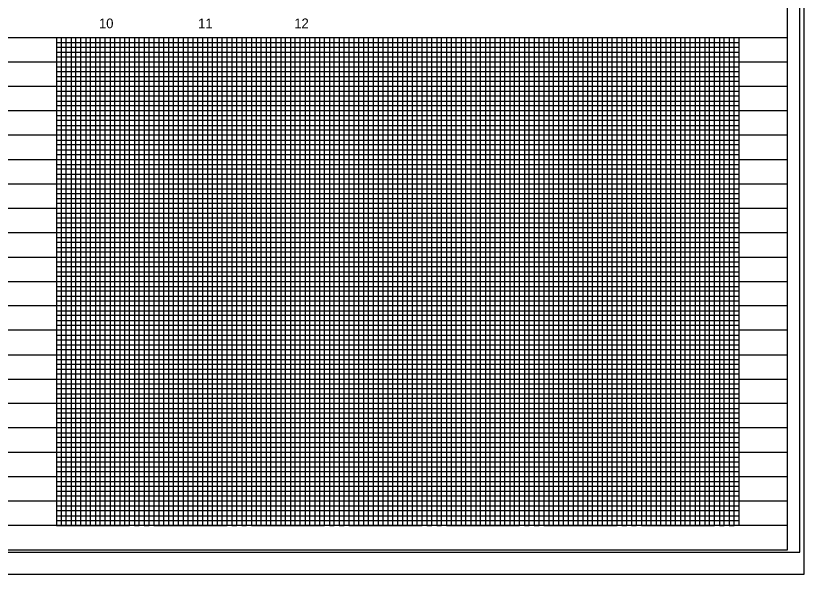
# Model space of a CAD drawing. Extents: x 1019474 to 1021158, y 503201 to 504732.
# Drawn here: x 1020350 to 1021158, y 503201 to 503773 of the extents above; entities that cross this region are included whole.
import ezdxf

# ---------------------------------------------------------------- set-up
doc = ezdxf.new("R2010")
doc.units = 0
for name, color, linetype in [('Exist Vertical Profile Horizontal Axis Label Major', 7, 'Continuous'), ('Sheet Cutting Line CELL', 7, 'Continuous'), ('Sheet Layout Profile Border Port 2', 7, 'Continuous'), ('Sheet Plot Border Inside CELL', 7, 'Continuous'), ('Sheet Plot Border Outside CELL', 7, 'Continuous'), ('Sheet Profile CELL', 7, 'Continuous'), ('Sheet Profile Grid Major CELL', 7, 'Continuous'), ('Sheet Profile Grid Middle CELL', 7, 'Continuous'), ('Sheet Profile Grid Minor CELL', 7, 'Continuous')]:
    doc.layers.add(name, color=color, linetype=linetype)

msp = doc.modelspace()

# ---------------------------------------------------------------- linework, layer by layer
at = {"layer": 'Sheet Cutting Line CELL'}
msp.add_line((1019474.22, 503200.7), (1021158.22, 503200.7), dxfattribs=at)
at = {"layer": 'Sheet Layout Profile Border Port 2'}
msp.add_lwpolyline([(1019691.22, 503750.7), (1021091.22, 503750.7), (1021091.22, 503250.7), (1019691.22, 503250.7)], close=True, dxfattribs=at)
at = {"layer": 'Sheet Plot Border Inside CELL'}
msp.add_lwpolyline([(1019487.22, 503223.15), (1021153.72, 503223.15), (1021153.72, 504278.25), (1019487.22, 504278.25)], close=True, dxfattribs=at)
at = {"layer": 'Sheet Plot Border Outside CELL'}
msp.add_lwpolyline([(1019474.22, 503200.7), (1021158.22, 503200.7), (1021158.22, 504300.7), (1019474.22, 504300.7)], close=True, dxfattribs=at)
at = {"layer": 'Sheet Profile CELL'}
for p, q in [((1019641.22, 503750.7), (1021141.22, 503750.7)), ((1021141.22, 503250.7), (1019641.22, 503250.7)), ((1019641.22, 503225.7), (1021141.22, 503225.7))]:
    msp.add_line(p, q, dxfattribs=at)
msp.add_lwpolyline([(1021141.22, 504275.7), (1019641.22, 504275.7), (1019641.22, 503225.7), (1021141.22, 503225.7)], close=True, dxfattribs=at)
at = {"layer": 'Sheet Profile Grid Major CELL'}
for p, q in [((1020341.22, 503750.7), (1020391.22, 503750.7)), ((1020441.22, 503750.7), (1020491.22, 503750.7)), ((1020541.22, 503750.7), (1020591.22, 503750.7)), ((1020641.22, 503750.7), (1020691.22, 503750.7)), ((1020741.22, 503750.7), (1020791.22, 503750.7)), ((1020841.22, 503750.7), (1020891.22, 503750.7)), ((1020941.22, 503750.7), (1020991.22, 503750.7)), ((1021041.22, 503750.7), (1021091.22, 503750.7)), ((1021041.22, 503250.7), (1021041.22, 503250.7))]:
    msp.add_line(p, q, dxfattribs=at)
for points in [[(1020341.22, 503750.7), (1020391.22, 503750.7), (1020391.22, 503250.7), (1020441.22, 503250.7), (1020441.22, 503750.7), (1020491.22, 503750.7), (1020491.22, 503250.7), (1020541.22, 503250.7), (1020541.22, 503750.7), (1020591.22, 503750.7), (1020591.22, 503250.7), (1020641.22, 503250.7), (1020641.22, 503750.7), (1020691.22, 503750.7), (1020691.22, 503250.7), (1020741.22, 503250.7), (1020741.22, 503750.7), (1020791.22, 503750.7), (1020791.22, 503250.7), (1020841.22, 503250.7), (1020841.22, 503750.7), (1020891.22, 503750.7), (1020891.22, 503250.7), (1020941.22, 503250.7), (1020941.22, 503750.7), (1020991.22, 503750.7), (1020991.22, 503250.7), (1021041.22, 503250.7), (1021041.22, 503250.7), (1021041.22, 503750.7), (1021091.22, 503750.7), (1021091.22, 503250.7)], [(1021141.22, 503700.7), (1019641.22, 503700.7)], [(1021141.22, 503650.7), (1019641.22, 503650.7), (1019641.22, 503600.7), (1021141.22, 503600.7)], [(1021141.22, 503550.7), (1019641.22, 503550.7), (1019641.22, 503500.7), (1021141.22, 503500.7)], [(1021141.22, 503450.7), (1019641.22, 503450.7), (1019641.22, 503400.7), (1021141.22, 503400.7)], [(1021141.22, 503350.7), (1019641.22, 503350.7), (1019641.22, 503350.7), (1019641.22, 503300.7), (1021141.22, 503300.7)], [(1021141.22, 503250.7), (1019641.22, 503250.7)]]:
    msp.add_lwpolyline(points, dxfattribs=at)
at = {"layer": 'Sheet Profile Grid Middle CELL'}
for points in [[(1020391.22, 503250.7), (1020416.22, 503250.7), (1020416.22, 503750.7), (1020441.22, 503750.7)], [(1020441.22, 503250.7), (1020466.22, 503250.7), (1020466.22, 503750.7), (1020516.22, 503750.7), (1020516.22, 503250.7), (1020566.22, 503250.7), (1020566.22, 503750.7), (1020616.22, 503750.7), (1020616.22, 503250.7), (1020666.22, 503250.7), (1020666.22, 503750.7), (1020716.22, 503750.7), (1020716.22, 503250.7), (1020766.22, 503250.7), (1020766.22, 503750.7), (1020816.22, 503750.7), (1020816.22, 503250.7), (1020866.22, 503250.7), (1020866.22, 503750.7), (1020916.22, 503750.7), (1020916.22, 503250.7), (1020966.22, 503250.7), (1020966.22, 503750.7), (1021016.22, 503750.7), (1021016.22, 503250.7), (1021066.22, 503250.7), (1021066.22, 503750.7)], [(1019641.22, 503725.7), (1021141.22, 503725.7)], [(1021141.22, 503675.7), (1019641.22, 503675.7), (1019641.22, 503625.7), (1021141.22, 503625.7)], [(1021141.22, 503575.7), (1019641.22, 503575.7), (1019641.22, 503525.7), (1021141.22, 503525.7)], [(1021141.22, 503475.7), (1019641.22, 503475.7), (1019641.22, 503425.7), (1021141.22, 503425.7)], [(1021141.22, 503375.7), (1019641.22, 503375.7), (1019641.22, 503325.7), (1021141.22, 503325.7)], [(1021141.22, 503275.7), (1019641.22, 503275.7)]]:
    msp.add_lwpolyline(points, dxfattribs=at)
at = {"layer": 'Sheet Profile Grid Minor CELL'}
for p, q in [((1020391.22, 503745.7), (1020441.22, 503745.7)), ((1020441.22, 503740.7), (1020391.22, 503740.7)), ((1020441.22, 503745.7), (1021091.22, 503745.7)), ((1021091.22, 503740.7), (1020441.22, 503740.7)), ((1020391.22, 503735.7), (1020441.22, 503735.7)), ((1020441.22, 503735.7), (1021091.22, 503735.7)), ((1020441.22, 503730.7), (1020391.22, 503730.7)), ((1021091.22, 503730.7), (1020441.22, 503730.7)), ((1020391.22, 503720.7), (1020441.22, 503720.7)), ((1020441.22, 503715.7), (1020391.22, 503715.7)), ((1020441.22, 503720.7), (1021091.22, 503720.7)), ((1021091.22, 503715.7), (1020441.22, 503715.7)), ((1020391.22, 503710.7), (1020441.22, 503710.7)), ((1020441.22, 503710.7), (1021091.22, 503710.7)), ((1020441.22, 503705.7), (1020391.22, 503705.7)), ((1021091.22, 503705.7), (1020441.22, 503705.7)), ((1020391.22, 503695.7), (1020441.22, 503695.7)), ((1020441.22, 503695.7), (1021091.22, 503695.7)), ((1020441.22, 503690.7), (1020391.22, 503690.7)), ((1020391.22, 503685.7), (1020441.22, 503685.7)), ((1021091.22, 503690.7), (1020441.22, 503690.7)), ((1020441.22, 503685.7), (1021091.22, 503685.7)), ((1020441.22, 503680.7), (1020391.22, 503680.7)), ((1021091.22, 503680.7), (1020441.22, 503680.7)), ((1020391.22, 503670.7), (1020441.22, 503670.7)), ((1020441.22, 503670.7), (1021091.22, 503670.7)), ((1020441.22, 503665.7), (1020391.22, 503665.7)), ((1020391.22, 503660.7), (1020441.22, 503660.7)), ((1021091.22, 503665.7), (1020441.22, 503665.7)), ((1020441.22, 503660.7), (1021091.22, 503660.7)), ((1020441.22, 503655.7), (1020391.22, 503655.7)), ((1021091.22, 503655.7), (1020441.22, 503655.7)), ((1020391.22, 503645.7), (1020441.22, 503645.7)), ((1020441.22, 503645.7), (1021091.22, 503645.7)), ((1020441.22, 503640.7), (1020391.22, 503640.7)), ((1020391.22, 503635.7), (1020441.22, 503635.7)), ((1021091.22, 503640.7), (1020441.22, 503640.7)), ((1020441.22, 503635.7), (1021091.22, 503635.7)), ((1020441.22, 503630.7), (1020391.22, 503630.7)), ((1021091.22, 503630.7), (1020441.22, 503630.7)), ((1020391.22, 503620.7), (1020441.22, 503620.7)), ((1020441.22, 503620.7), (1021091.22, 503620.7)), ((1020441.22, 503615.7), (1020391.22, 503615.7)), ((1020391.22, 503610.7), (1020441.22, 503610.7)), ((1021091.22, 503615.7), (1020441.22, 503615.7)), ((1020441.22, 503610.7), (1021091.22, 503610.7)), ((1020441.22, 503605.7), (1020391.22, 503605.7)), ((1021091.22, 503605.7), (1020441.22, 503605.7)), ((1020391.22, 503595.7), (1020441.22, 503595.7)), ((1020441.22, 503595.7), (1021091.22, 503595.7)), ((1020441.22, 503590.7), (1020391.22, 503590.7)), ((1020391.22, 503585.7), (1020441.22, 503585.7)), ((1021091.22, 503590.7), (1020441.22, 503590.7)), ((1020441.22, 503585.7), (1021091.22, 503585.7)), ((1020441.22, 503580.7), (1020391.22, 503580.7)), ((1021091.22, 503580.7), (1020441.22, 503580.7)), ((1020391.22, 503570.7), (1020441.22, 503570.7)), ((1020441.22, 503570.7), (1021091.22, 503570.7)), ((1020441.22, 503565.7), (1020391.22, 503565.7)), ((1021091.22, 503565.7), (1020441.22, 503565.7)), ((1020391.22, 503560.7), (1020441.22, 503560.7)), ((1020441.22, 503555.76), (1020391.22, 503555.77)), ((1020441.22, 503560.7), (1021091.22, 503560.7)), ((1021091.22, 503555.7), (1020441.22, 503555.77)), ((1020391.22, 503545.7), (1020441.22, 503545.7)), ((1020441.22, 503545.7), (1021091.22, 503545.7)), ((1020441.22, 503540.7), (1020391.22, 503540.7)), ((1021091.22, 503540.7), (1020441.22, 503540.7)), ((1020391.22, 503535.7), (1020441.22, 503535.7)), ((1020441.22, 503530.7), (1020391.22, 503530.7)), ((1020441.22, 503535.7), (1021091.22, 503535.7)), ((1021091.22, 503530.7), (1020441.22, 503530.7)), ((1020391.22, 503520.7), (1020441.22, 503520.7)), ((1020441.22, 503515.7), (1020391.22, 503515.7)), ((1020441.22, 503520.7), (1021091.22, 503520.7)), ((1021091.22, 503515.7), (1020441.22, 503515.7)), ((1020391.22, 503510.7), (1020441.22, 503510.7)), ((1020441.22, 503505.7), (1020391.22, 503505.7)), ((1020441.22, 503510.7), (1021091.22, 503510.7)), ((1021091.22, 503505.7), (1020441.22, 503505.7)), ((1020391.22, 503495.7), (1020441.22, 503495.7)), ((1020441.22, 503490.7), (1020391.22, 503490.7)), ((1020441.22, 503495.7), (1021091.22, 503495.7)), ((1021091.22, 503490.7), (1020441.22, 503490.7)), ((1020391.22, 503485.7), (1020441.22, 503485.7)), ((1020441.22, 503480.7), (1020391.22, 503480.7)), ((1020441.22, 503485.7), (1021091.22, 503485.7)), ((1021091.22, 503480.7), (1020441.22, 503480.7)), ((1020391.22, 503470.7), (1020441.22, 503470.7)), ((1020441.22, 503465.7), (1020391.22, 503465.7)), ((1020441.22, 503470.7), (1021091.22, 503470.7)), ((1021091.22, 503465.7), (1020441.22, 503465.7)), ((1020391.22, 503460.7), (1020441.22, 503460.7)), ((1020441.22, 503460.7), (1021091.22, 503460.7)), ((1020441.22, 503455.7), (1020391.22, 503455.7)), ((1021091.22, 503455.7), (1020441.22, 503455.7)), ((1020391.22, 503445.7), (1020441.22, 503445.7)), ((1020441.22, 503440.7), (1020391.22, 503440.7)), ((1020441.22, 503445.7), (1021091.22, 503445.7)), ((1021091.22, 503440.7), (1020441.22, 503440.7)), ((1020391.22, 503435.7), (1020441.22, 503435.7)), ((1020441.22, 503435.7), (1021091.22, 503435.7)), ((1020441.22, 503430.7), (1020391.22, 503430.7)), ((1021091.22, 503430.7), (1020441.22, 503430.7)), ((1020391.22, 503420.7), (1020441.22, 503420.7)), ((1020441.22, 503420.7), (1021091.22, 503420.7)), ((1020441.22, 503415.7), (1020391.22, 503415.7)), ((1020391.22, 503410.7), (1020441.22, 503410.7)), ((1021091.22, 503415.7), (1020441.22, 503415.7)), ((1020441.22, 503410.7), (1021091.22, 503410.7)), ((1020441.22, 503405.7), (1020391.22, 503405.7)), ((1021091.22, 503405.7), (1020441.22, 503405.7)), ((1020391.22, 503395.7), (1020441.22, 503395.7)), ((1020441.22, 503395.7), (1021091.22, 503395.7)), ((1020441.22, 503390.7), (1020391.22, 503390.7)), ((1020391.22, 503385.7), (1020441.22, 503385.7)), ((1021091.22, 503390.7), (1020441.22, 503390.7)), ((1020441.22, 503385.7), (1021091.22, 503385.7)), ((1020441.22, 503380.7), (1020391.22, 503380.7)), ((1021091.22, 503380.7), (1020441.22, 503380.7)), ((1020391.22, 503370.7), (1020441.22, 503370.7)), ((1020441.22, 503370.7), (1021091.22, 503370.7)), ((1020441.22, 503365.7), (1020391.22, 503365.7)), ((1020391.22, 503360.7), (1020441.22, 503360.7)), ((1021091.22, 503365.7), (1020441.22, 503365.7)), ((1020441.22, 503360.7), (1021091.22, 503360.7)), ((1020441.22, 503355.7), (1020391.22, 503355.7)), ((1021091.22, 503355.7), (1020441.22, 503355.7)), ((1020391.22, 503345.7), (1020441.22, 503345.7)), ((1020441.22, 503345.7), (1021091.22, 503345.7)), ((1020441.22, 503340.7), (1020391.22, 503340.7)), ((1020391.22, 503335.7), (1020441.22, 503335.7)), ((1021091.22, 503340.7), (1020441.22, 503340.7)), ((1020441.22, 503335.7), (1021091.22, 503335.7)), ((1020441.22, 503330.7), (1020391.22, 503330.7)), ((1021091.22, 503330.7), (1020441.22, 503330.7)), ((1020391.22, 503320.7), (1020441.22, 503320.7)), ((1020441.22, 503320.7), (1021091.22, 503320.7)), ((1020441.22, 503315.7), (1020391.22, 503315.7)), ((1020391.22, 503310.7), (1020441.22, 503310.7)), ((1021091.22, 503315.7), (1020441.22, 503315.7)), ((1020441.22, 503310.7), (1021091.22, 503310.7)), ((1020441.22, 503305.7), (1020391.22, 503305.7)), ((1021091.22, 503305.7), (1020441.22, 503305.7)), ((1020391.22, 503295.7), (1020441.22, 503295.7)), ((1020441.22, 503295.7), (1021091.22, 503295.7)), ((1020441.22, 503290.7), (1020391.22, 503290.7)), ((1021091.22, 503290.7), (1020441.22, 503290.7)), ((1020391.22, 503285.7), (1020441.22, 503285.7)), ((1020441.22, 503280.7), (1020391.22, 503280.7)), ((1020441.22, 503285.7), (1021091.22, 503285.7)), ((1021091.22, 503280.7), (1020441.22, 503280.7)), ((1020391.22, 503270.7), (1020441.22, 503270.7)), ((1020441.22, 503270.7), (1021091.22, 503270.7)), ((1020441.22, 503265.7), (1020391.22, 503265.7)), ((1021091.22, 503265.7), (1020441.22, 503265.7)), ((1020391.22, 503260.7), (1020441.22, 503260.7)), ((1020391.22, 503255.7), (1020441.22, 503255.7)), ((1020441.22, 503260.7), (1021091.22, 503260.7)), ((1020441.22, 503255.7), (1021091.22, 503255.7)), ((1021091.22, 503255.7), (1021091.22, 503255.7))]:
    msp.add_line(p, q, dxfattribs=at)
for points in [[(1020391.22, 503750.7), (1020396.22, 503750.7), (1020396.22, 503250.7), (1020401.22, 503250.7), (1020401.22, 503750.7), (1020406.22, 503750.7), (1020406.22, 503250.7), (1020411.22, 503250.7), (1020411.22, 503750.7), (1020421.22, 503750.7), (1020421.22, 503250.7), (1020426.22, 503250.7), (1020426.22, 503750.7), (1020431.22, 503750.7), (1020431.22, 503250.7), (1020436.22, 503250.7), (1020436.22, 503750.7), (1020441.22, 503750.7)], [(1020441.22, 503750.7), (1020446.22, 503750.7), (1020446.22, 503250.7), (1020451.22, 503250.7), (1020451.22, 503750.7), (1020456.22, 503750.7), (1020456.22, 503250.7), (1020461.22, 503250.7), (1020461.22, 503750.7), (1020471.22, 503750.7), (1020471.22, 503250.7), (1020476.22, 503250.7), (1020476.22, 503750.7), (1020481.22, 503750.7), (1020481.22, 503250.7), (1020486.22, 503250.7), (1020486.22, 503750.7), (1020496.22, 503750.7), (1020496.22, 503250.7), (1020500.92, 503251.25), (1020501.22, 503250.7), (1020501.22, 503750.7), (1020506.22, 503750.7), (1020506.22, 503250.7), (1020511.22, 503250.7), (1020511.22, 503750.7), (1020521.22, 503750.7), (1020521.22, 503250.7), (1020526.22, 503250.7)], [(1020526.22, 503250.7), (1020526.22, 503750.7), (1020531.22, 503750.7), (1020531.22, 503250.7), (1020536.22, 503250.7), (1020536.22, 503750.7), (1020546.22, 503750.7), (1020546.22, 503250.7), (1020551.22, 503250.7), (1020551.22, 503750.7), (1020556.22, 503750.7), (1020556.22, 503250.7), (1020561.22, 503250.7), (1020561.22, 503750.7), (1020571.22, 503750.7), (1020571.22, 503250.7), (1020576.22, 503250.7), (1020576.22, 503750.7), (1020581.22, 503750.7), (1020581.22, 503250.7), (1020586.22, 503250.7), (1020586.22, 503750.7), (1020596.22, 503750.7), (1020596.22, 503250.7), (1020601.22, 503250.7), (1020601.22, 503750.7), (1020606.22, 503750.7), (1020606.22, 503250.7), (1020611.22, 503250.7), (1020611.22, 503750.7), (1020621.22, 503750.7), (1020621.22, 503250.7), (1020626.22, 503250.7), (1020626.22, 503750.7), (1020631.22, 503750.7), (1020631.22, 503250.7), (1020636.22, 503250.7), (1020636.22, 503750.7), (1020646.22, 503750.7), (1020646.22, 503250.7), (1020651.22, 503250.7), (1020651.22, 503750.7), (1020656.22, 503750.7), (1020656.22, 503250.7), (1020661.22, 503250.7), (1020661.22, 503750.7), (1020671.22, 503750.7), (1020671.22, 503250.7), (1020676.22, 503250.7), (1020676.22, 503750.7), (1020681.22, 503750.7), (1020681.22, 503250.7), (1020686.22, 503250.7), (1020686.22, 503750.7), (1020696.22, 503750.7), (1020696.22, 503250.7), (1020701.22, 503250.7), (1020701.22, 503750.7), (1020706.22, 503750.7), (1020706.22, 503250.7), (1020711.22, 503250.7), (1020711.22, 503750.7), (1020721.22, 503750.7), (1020721.22, 503250.7), (1020726.22, 503250.7), (1020726.22, 503750.7), (1020731.22, 503750.7), (1020731.22, 503250.7), (1020736.22, 503250.7), (1020736.22, 503750.7), (1020746.22, 503750.7), (1020746.22, 503250.7), (1020751.22, 503250.7), (1020751.22, 503750.7), (1020756.22, 503750.7), (1020756.22, 503250.7), (1020761.22, 503250.7), (1020761.22, 503750.7), (1020771.22, 503750.7), (1020771.22, 503250.7), (1020776.22, 503250.7), (1020776.22, 503750.7), (1020781.22, 503750.7), (1020781.22, 503250.7), (1020786.22, 503250.7), (1020786.22, 503750.7), (1020796.22, 503750.7), (1020796.22, 503250.7), (1020801.22, 503250.7), (1020801.22, 503750.7), (1020806.22, 503750.7), (1020806.22, 503250.7), (1020811.22, 503250.7), (1020811.22, 503750.7), (1020821.22, 503750.7), (1020821.22, 503250.7), (1020826.22, 503250.7), (1020826.22, 503750.7), (1020831.22, 503750.7), (1020831.22, 503250.7)], [(1020831.22, 503250.7), (1020836.22, 503250.7), (1020836.22, 503750.7), (1020846.22, 503750.7), (1020846.22, 503250.7), (1020851.22, 503250.7), (1020851.22, 503750.7), (1020856.22, 503750.7), (1020856.22, 503250.7), (1020861.22, 503250.7), (1020861.22, 503750.7), (1020871.22, 503750.7), (1020871.22, 503250.7), (1020876.22, 503250.7), (1020876.22, 503750.7), (1020881.22, 503750.7), (1020881.22, 503250.7), (1020886.22, 503250.7), (1020886.22, 503750.7), (1020896.22, 503750.7), (1020896.22, 503250.7), (1020901.22, 503250.7), (1020901.22, 503750.7), (1020906.22, 503750.7), (1020906.22, 503250.7), (1020911.22, 503250.7), (1020911.22, 503750.7), (1020921.22, 503750.7), (1020921.22, 503250.7), (1020926.22, 503250.7), (1020926.22, 503750.7), (1020931.22, 503750.7), (1020931.22, 503250.7), (1020936.22, 503250.7), (1020936.22, 503750.7), (1020946.22, 503750.7), (1020946.22, 503250.7), (1020951.22, 503250.7), (1020951.22, 503750.7), (1020956.22, 503750.7), (1020956.22, 503250.7), (1020961.22, 503250.7), (1020961.22, 503750.7), (1020971.22, 503750.7), (1020971.22, 503250.7), (1020976.22, 503250.7), (1020976.22, 503750.7), (1020981.22, 503750.7), (1020981.22, 503250.7), (1020986.22, 503250.7), (1020986.22, 503750.7), (1020996.22, 503750.7), (1020996.22, 503250.7), (1021001.22, 503250.7), (1021001.22, 503750.7), (1021006.22, 503750.7), (1021006.22, 503250.7), (1021011.22, 503250.7), (1021011.22, 503750.7), (1021021.22, 503750.7), (1021021.22, 503250.7), (1021026.22, 503250.7), (1021026.22, 503750.7), (1021031.22, 503750.7), (1021031.22, 503250.7), (1021036.22, 503250.7), (1021036.22, 503750.7), (1021046.22, 503750.7), (1021046.22, 503250.7), (1021051.22, 503250.7), (1021051.22, 503750.7), (1021056.22, 503750.7), (1021056.22, 503250.7), (1021061.22, 503250.7), (1021061.22, 503750.7), (1021071.22, 503750.7), (1021071.22, 503250.7), (1021076.22, 503250.7), (1021076.22, 503750.7), (1021081.22, 503750.7), (1021081.22, 503250.7), (1021086.22, 503250.7), (1021086.22, 503750.7), (1021091.22, 503750.7)]]:
    msp.add_lwpolyline(points, dxfattribs=at)

# ---------------------------------------------------------------- texts
at = {"layer": 'Exist Vertical Profile Horizontal Axis Label Major'}
for s, p in [('10', (1020434.81, 503760.26)), ('11', (1020536.57, 503760.26)), ('12', (1020635.14, 503760.26))]:
    msp.add_text(s, height=10, dxfattribs=at).set_placement(p)

doc.saveas('drawing.dxf')
